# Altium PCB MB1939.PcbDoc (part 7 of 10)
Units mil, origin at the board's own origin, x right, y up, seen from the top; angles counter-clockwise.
Board outline 5910.64 x 4335.93 mil, 6 copper layers (Top Layer, l2_GND, L3_SIG, L4_VCC, L5_GND, Bottom Layer), stack 58.424 mil thick; 635 components, 489 nets, 2289 pads, 1388 vias.
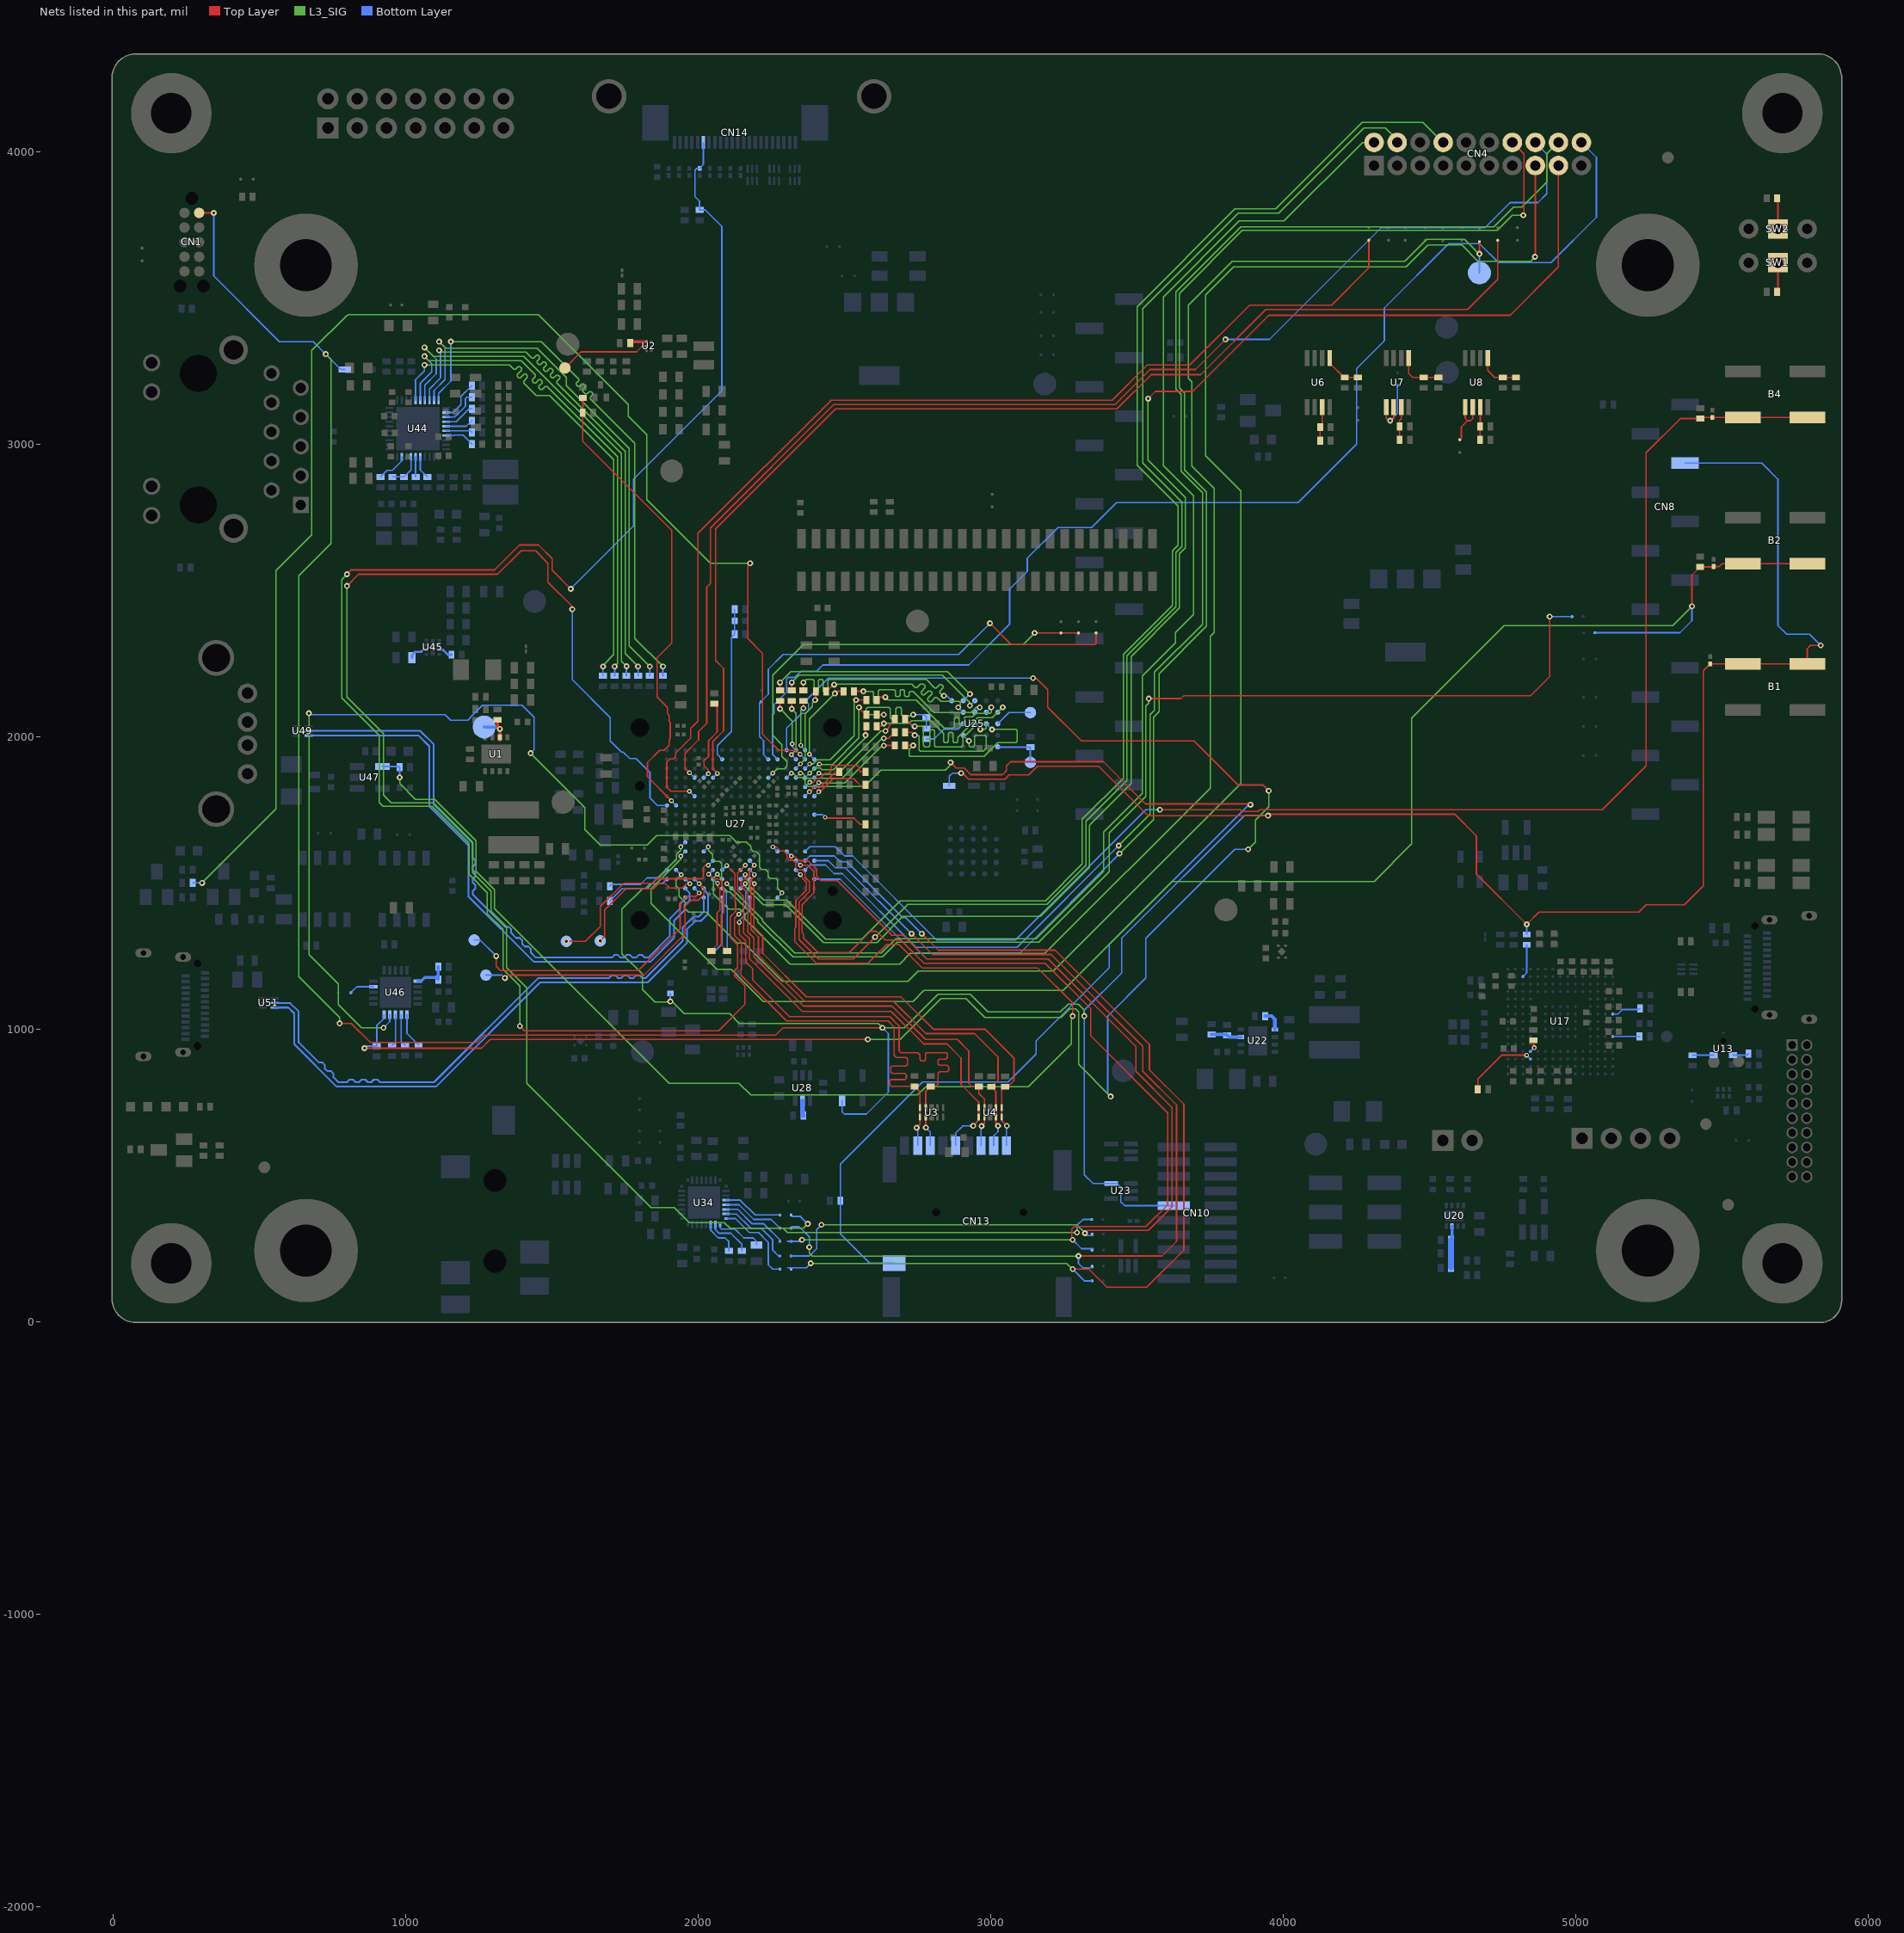
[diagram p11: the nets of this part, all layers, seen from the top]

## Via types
v1: diameter 20, hole 10, Top Layer to Bottom Layer, tented both sides, 1072 vias
v2: diameter 16, hole 8, Top Layer to Bottom Layer, tented both sides, 316 vias

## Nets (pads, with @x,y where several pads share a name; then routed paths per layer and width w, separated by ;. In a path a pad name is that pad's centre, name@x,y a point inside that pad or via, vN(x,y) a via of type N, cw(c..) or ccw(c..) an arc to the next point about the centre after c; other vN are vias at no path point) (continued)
NetR12_2: R12.2 TP12.1 U1.2 | length 129.9
  Top Layer w10: R12.2@1315,2057.28 1315,2034 v1(1322.8,2026.2) U1.2@1322.8,1998.07 1322.8,1987.31 1322.73,1987.24
  Bottom Layer w10: TP12.1@1269,2033 1316,2033 v1(1322.8,2026.2)
NetR25_2: R25.2 U2.A1 | length 58.6
  Top Layer w10: R25.2@1767.72,3345 1772.72,3350 U2.A1@1824.25,3350
NetR26_1: R26.1 U17.C4 | length 253.7
  Top Layer w5: R26.1@4664.57,795 4664.57,830 4745.81,911.25 v2(4831.55,911.25)
  Bottom Layer w5: v2(4831.55,911.25) U17.C4@4844.33,898.47
NetR32_1: R32.1 U27.C6 | length 268.7
  Top Layer w5: R32.1@2045,1267.72 2065.28,1288 2065.28,1397.28 2075,1407 2075,1480 2066.49,1488.51 v2(2066.49,1499)
  Bottom Layer w5: U27.C6@2050.86,1513.03 2064.89,1499 v2(2066.49,1499)
NetR33_1: R33.1 U27.P5 | length 289.9
  Top Layer w5: v2(2035.49,1873.2) 2035.49,1875.62 2035,1876.11 2035,1886.19 2020.51,1900.68 2020.51,1917.5 2035.91,1932.9 2035.91,1986.21 2065.3,2015.6 2065.3,2101.98 R33.1@2055,2112.28
  Bottom Layer w5: U27.P5@2019.36,1859.49 2033.07,1873.2 v2(2035.49,1873.2)
NetR34_1: R34.1 U27.D6 | length 327.4
  Top Layer w5: v2(2035.9,1529.83) 2038.18,1529.83 2054.51,1513.5 2072.5,1513.5 2080.99,1505.01 2080.99,1490.01 2087,1484 2087,1398 2080,1391 2080,1287.72 R34.1@2100,1267.72
  Bottom Layer w5: v2(2035.9,1529.83) 2036.16,1529.83 U27.D6@2050.86,1544.53
NetR81_2: R81.2 R82.2 U6.3 | length 117.2
  Top Layer w5: R81.2@4125.8,3012.01 R82.2@4125.8,3058.01 4132.8,3065.02 U6.3@4132.8,3126.34
NetR83_2: R83.2 R84.2 U6.5 | length 133.9
  Top Layer w5: U6.5@4158.39,3293.66 4158.39,3276.61 4207.28,3227.72 R84.2@4255,3227.72
NetR85_2: R85.2 R86.2 U7.3 | length 113.6
  Top Layer w5: R85.2@4397.29,3015 4397.28,3081.28 4402.8,3086.8 U7.3@4402.8,3126.34
NetR87_2: R87.2 R88.2 U7.5 | length 159.4
  Top Layer w5: U7.5@4428.39,3293.66 4428.39,3241.61 4442.28,3227.72 R88.2@4530,3227.72
NetR89_2: R89.2 R90.2 U8.3 | length 111.6
  Top Layer w5: R89.2@4672.29,3015 R90.2@4672.29,3060 4672.8,3060.52 U8.3@4672.8,3126.34
NetR91_2: R91.2 R92.2 U8.5 | length 148.6
  Top Layer w5: U8.5@4698.39,3293.66 4698.39,3251.61 4722.28,3227.72 R92.2@4795,3227.72
NetR93_1: R93.1 U17.D4 | length 44.4
  Top Layer w5: R93.1@4855,962.28 4855,938.95 v2(4857.11,936.84)
  Bottom Layer w5: U17.D4@4844.33,924.06 v2(4857.11,936.84)
NetR102_1: R102.1 SW1.1 | length 100.9
  Top Layer w5: R102.1@5687.72,3520 5690,3522.28 SW1.1@5690,3620
NetR103_1: R103.1 SW2.1 | length 105.9
  Top Layer w5: R103.1@5687.72,3840 5690,3837.72 SW2.1@5690,3735
NetR104_1: R104.1 U13.4 | length 55
  Bottom Layer w5: U13.4@5536.68,911.66 5584.81,911.66 R104.1@5589.67,916.51
NetR106_2: R106.2 U13.2 | length 72.4
  Bottom Layer w5: R106.2@5398.68,910.72 5399.62,911.66 U13.2@5470.69,911.66
NetR109_1: R109.1 U17.J15 | length 101.2
  Bottom Layer w5: U17.J15@5125.83,1052.01 5143.46,1052 5158.85,1067.39 5214.94,1067.39 R109.1@5218.98,1071.42
NetR110_1: R110.1 U17.F15 | length 91.6
  Bottom Layer w5: U17.F15@5125.83,975.24 5217.04,975.24 R110.1@5217.29,975
NetR117_1: R117.1 U17.P3 | length 114.1
  Bottom Layer w5: U17.P3@4818.74,1179.96 4831.69,1192.91 R117.1@4831.69,1288.7
NetR126_1: R126.1 R127.1 R128.1 U20.7 | length 143.4
  Bottom Layer w10: R128.1@4572.72,280 4576.14,283.42 U20.7@4576.14,327.01
  Bottom Layer w20: R126.1@4572.72,185 R128.1@4572.72,280
NetR132_1: R132.1 U22.5 | length 73
  Bottom Layer w12: R132.1@3937.72,1045 3960,1045 3971.06,1033.94 U22.5@3971.07,998.89
NetR133_2: R133.2 R135.1 U22.3 | length 103.6
  Bottom Layer w12: R135.1@3755,982.28 3805.08,982.28 3814.05,973.31 U22.3@3854.92,973.3
NetR139_1: R139.1 TP6.1 U25.A5 | length 163.9
  Bottom Layer w5: U25.A5@3024.25,1965.27 3025.23,1964.29 R139.1@3135.51,1964.29 TP6.1@3135.51,1912.01
NetR141_2: R141.2 U25.C2 | length 147.6
  Bottom Layer w5: R141.2@2780,1992.28 2807.28,1992.28 2840,2025 2887.13,2025 U25.C2@2906.14,2044.01
NetR146_1: R146.1 U28.5 | length 52.8
  Bottom Layer w15: U28.5@2357.02,756.18 2357.01,707.21 R146.1@2359.73,704.49
NetR147_1: R147.1 U34.1 | length 164.4
  Bottom Layer w5: U34.1@2074.76,329.23 2074.76,322.14 2079.6,317.3 2125.9,317.3 2156.4,286.8 2188.3,286.8 2200,275.1 R147.1@2200,262.56
NetR160_2: R160.2 U44.20 | length 1908.8
  L3_SIG w4: v1(1155,3350) 1464,3350 1591.79,3222.21 1591.79,3216.55 1583.45,3208.21 1583.45,3202.55 1589.11,3196.89 1594.77,3196.89 1603.11,3205.23 1608.77,3205.23 1614.43,3199.57 1614.43,3193.91 1606.09,3185.57 1606.09,3179.91 1614.61,3171.39 1620.27,3171.39 1628.61,3179.73 1634.27,3179.73 1639.93,3174.07 1639.93,3168.41 1631.59,3160.07 1631.59,3154.41 1784,3002 1784,2336 v1(1880,2240)
  Bottom Layer w5: U44.20@1113.5,3149.29 1113.5,3173.5 1155,3215 v1(1155,3350) ; R160.2@1880,2207.72 v1(1880,2240)
NetR161_2: R161.2 U44.19 | length 1847.7
  L3_SIG w4: v1(1115,3350) 1138,3327 1450,3327 1550,3227 1550,3199 1764,2985 1764,2311 v1(1835,2240)
  Bottom Layer w5: U44.19@1097.75,3149.29 1097.75,3182.75 1135,3220 1135,3330 v1(1115,3350) ; R161.2@1835,2207.72 v1(1835,2240)
NetR162_2: R162.2 U44.18 | length 1885.7
  L3_SIG w4: v1(1115,3320) 1120,3315 1412,3315 1432.86,3294.14 1438.52,3294.14 1447.86,3303.48 1453.52,3303.48 1459.18,3297.82 1459.18,3292.16 1449.84,3282.82 1449.84,3277.16 1455.5,3271.5 1461.16,3271.5 1470.5,3280.84 1476.16,3280.84 1481.82,3275.18 1481.82,3269.52 1472.48,3260.18 1472.48,3254.52 1478.14,3248.86 1483.8,3248.86 1493.14,3258.2 1498.8,3258.2 1504.46,3252.54 1504.46,3246.88 1495.12,3237.54 1495.12,3231.88 1500.78,3226.22 1506.44,3226.22 1515.78,3235.56 1521.44,3235.56 1527.1,3229.9 1527.1,3224.24 1517.76,3214.9 1517.76,3209.24 1751.52,2975.48 1751.52,2283.48 v1(1795,2240)
  Bottom Layer w5: U44.18@1082.01,3149.29 1082,3188.22 1120,3226.22 1120,3315 v1(1115,3320) ; R162.2@1795,2207.72 v1(1795,2240)
NetR166_2: R166.2 U44.17 | length 1803.4
  L3_SIG w4: v1(1065,3330) 1095,3300 1405,3300 1738,2967 1738,2258.04 v1(1755.52,2240.52)
  Bottom Layer w5: v1(1065,3330) 1105,3290 1105,3240 1066.25,3201.25 U44.17@1066.25,3149.29 ; R166.2@1755,2207.72 1755,2240 v1(1755.52,2240.52)
NetR169_2: R169.2 U44.16 | length 1806.5
  L3_SIG w4: v1(1065,3300) 1080,3285 1396,3285 1444.37,3236.63 1444.37,3230.97 1433.53,3220.13 1433.53,3214.47 1439.19,3208.81 1444.85,3208.81 1455.69,3219.65 1461.35,3219.65 1467.01,3213.99 1467.01,3208.33 1456.17,3197.49 1456.17,3191.83 1461.83,3186.17 1467.49,3186.17 1478.33,3197.01 1483.99,3197.01 1724.52,2956.48 1724.52,2249.52 v1(1715,2240)
  Bottom Layer w5: U44.16@1050.51,3149.29 1050.5,3206.72 1090,3246.22 1090,3275 v1(1065,3300) ; R169.2@1715,2207.72 v1(1715,2240)
NetR172_2: R172.2 U44.15 | length 1756.2
  L3_SIG w4: v1(1065,3270) 1356,3270 1370.69,3255.31 1376.35,3255.31 1385.69,3264.65 1391.35,3264.65 1397.01,3258.99 1397.01,3253.33 1381.67,3237.99 1381.67,3232.33 1387.33,3226.67 1392.99,3226.67 1405.33,3239.01 1410.99,3239.01 1416.65,3233.35 1416.65,3227.69 1403.81,3214.85 1403.81,3209.19 1447,3166 1493,3166 1712,2947 1712,2280.96 1675.52,2244.48 v1(1675.52,2240)
  Bottom Layer w5: U44.15@1034.76,3149.29 1034.76,3219.76 1065,3250 v1(1065,3270) ; R172.2@1675,2207.72 1675,2239.48 v1(1675.52,2240)
NetR180_2: R180.2 U44.27 | length 101.1
  Bottom Layer w5: U44.27@1139.09,3029.21 1164.47,3029.21 1165.46,3030.2 1197.08,3030.2 R180.2@1227.29,3000
NetR181_2: R181.2 U44.26 | length 90.2
  Bottom Layer w5: U44.26@1139.1,3044.95 1222.33,3044.95 R181.2@1227.29,3040
NetR182_2: R182.2 U44.25 | length 96.2
  Bottom Layer w5: U44.25@1139.09,3060.7 1207.65,3060.7 1226.95,3080 R182.2@1227.29,3080
NetR183_2: R183.2 U44.24 | length 106.2
  Bottom Layer w5: U44.24@1139.09,3076.45 1173.89,3076.45 1217.44,3120 R183.2@1227.29,3120
NetR184_2: R184.2 U44.23 | length 131.6
  Bottom Layer w5: U44.23@1139.09,3092.2 1168.42,3092.2 1205,3128.78 1205,3154.99 1210.01,3160 R184.2@1227.29,3160
NetR185_2: R185.2 U44.22 | length 142.6
  Bottom Layer w5: U44.22@1139.09,3107.95 1162.94,3107.94 1190,3135 1190,3162.71 R185.2@1227.29,3200
NetR189_2: R189.2 U45.3 | length 49.3
  Bottom Layer w7: U45.3@1115.2,2297.32 1127.43,2297.32
  Bottom Layer w8: 1127.43,2297.32 1144.75,2280 R189.2@1157.28,2280
NetR192_1: R192.1 R193.2 U46.11 | length 123.3
  Bottom Layer w10: U46.11@1041.8,1165.07 1055.07,1165.07 1066.5,1176.5 1104.79,1176.5 R192.1@1112.29,1169 R193.2@1112.29,1214
NetR196_2: R196.2 U44.35 | length 78.8
  Bottom Layer w5: U44.35@1050.51,2956.37 1050.5,2912.22 R196.2@1075,2887.72
NetR197_1: R197.1 U46.16 | length 120.1
  Bottom Layer w5: U46.16@1005.39,1049.91 1005.38,985.84 R197.1@1045.01,946.21
NetR198_2: R198.2 U44.36 | length 68.8
  Bottom Layer w5: U44.36@1034.76,2956.37 1034.76,2887.96 R198.2@1035,2887.72
NetR199_2: R199.2 U45.6 | length 65.8
  Bottom Layer w5: 1061.54,2297.32 U45.6@1071.89,2297.32
  Bottom Layer w8: R199.2@1022.56,2270 1022.56,2278.85 1033.71,2290 1054.22,2290 1061.54,2297.32
NetR202_2: R202.2 U46.17 | length 110.2
  Bottom Layer w5: U46.17@985.7,1049.91 985.69,958.53 R202.2@999.01,945.21
NetR203_1: R203.1 R205.2 U44.37 | length 118.6
  Bottom Layer w5: R205.2@955,2887.72 R203.1@995,2887.72 1019.01,2911.73 U44.37@1019.01,2956.37
NetR206_2: R206.2 U46.18 | length 110.7
  Bottom Layer w5: R206.2@954.01,944.21 966.01,956.21 U46.18@966.02,1049.91
NetR208_1: R208.1 U44.39 | length 109.1
  Bottom Layer w5: R208.1@915,2887.72 937.28,2910 955,2910 987.51,2942.51 U44.39@987.52,2956.37
NetR226_1: R226.1 U34.2 | length 151.2
  Bottom Layer w5: U34.2@2059.02,332.18 2059.02,314.98 2071.3,302.7 2112.3,302.7 2150,265 R226.1@2150,242.72
NetR227_1: R227.1 U34.3 | length 128.8
  Bottom Layer w5: U34.3@2043.27,332.18 2043.27,312.35 2068.74,286.87 2092.17,286.87 2105,274.04 R227.1@2105,242.72
NetSB47_2: SB47.2 U46.4 | length 85
  Bottom Layer w5: SB47.2@813.64,1125 834,1145.38 U46.4@890.23,1145.39
NetSB49_1: SB49.1 U8.1 U8.2 | length 178.2
  Top Layer w5: 4608,3020 4608,3058 4630,3080 ; U8.1@4621.61,3126.34 4621.61,3088.39 4630,3080 ; U8.2@4647.2,3126.34 4647.2,3087.2 4640,3080 4630,3080
NetSB51_1: SB51.1 U7.1 U7.2 | length 239.8
  Top Layer w5: U7.1@4351.61,3126.34 4351.61,3088.39 4360,3080 v1(4365,3080) 4370,3080 4377.2,3087.2 U7.2@4377.2,3126.34
  Bottom Layer w5: v1(4365,3080) 4390,3105 SB51.1@4390,3200.32
NetSB55_1: SB55.1 U34.28 | length 205.2
  Bottom Layer w5: U34.28@2095.43,415.84 2144.16,415.84 2195,365 SB55.1@2279.57,365
NetSB56_1: SB56.1 U34.29 | length 222.7
  Bottom Layer w5: U34.29@2095.43,400.1 2139.9,400.1 2190,350 2249.57,350 SB56.1@2279.57,320 2285,320
NetSB57_1: SB57.1 U34.30 | length 232.6
  Bottom Layer w5: U34.30@2095.43,384.35 2135.65,384.35 2185,335 2225,335 2279.57,280.43 SB57.1@2279.57,275
NetSB58_1: SB58.1 U34.32 | length 300.6
  Bottom Layer w5: U34.32@2095.43,352.85 2127.6,352.85 2175.45,305 2206.62,305 2240,271.62 2240,195 2255,180 SB58.1@2279.57,180
NetSB59_1: SB59.1 U34.31 | length 264.1
  Bottom Layer w5: U34.31@2095.43,368.6 2131.4,368.6 2180.26,319.74 2215.26,319.74 2255,280 2255,245 2275,225 SB59.1@2279.57,225
NetTP7_1: TP7.1 U25.C5 | length 127
  Bottom Layer w5: U25.C5@3024.25,2044.01 3062.25,2082.01 TP7.1@3135.51,2082.01
NetTP8_1: TP8.1 U27.C3 | length 474.5
  Top Layer w5: v1(1665.51,1302.01) 1681,1317.5 1681,1407.4 1753.6,1480 1847,1480 1864.3,1497.3 1888.61,1497.3 1903.11,1482.8 1934.45,1482.8 1934.49,1482.76 1946.51,1482.76 1961.05,1497.3 v2(1972.12,1497.3)
  Bottom Layer w5: U27.C3@1956.37,1513.03 v2(1972.12,1497.3)
NetTP9_1: TP9.1 U27.E6 | length 675.1
  Top Layer w5: v1(1550,1300) 1615,1300 1666,1351 1666,1419 1746,1499 1844,1499 1859,1514 2013,1514 2018,1519 2018,1522.48 2018.2,1522.68 2018.2,1534.7 2018,1534.9 2018,1552.99 2025.33,1560.32 v2(2035.09,1560.32)
  Bottom Layer w5: v2(2035.09,1560.32) 2050.8,1576.03 U27.E6@2050.86,1576.03
NetTP23_1: TP23.1 U27.C4 | length 989.2
  Top Layer w5: v1(1340,1175) 1350,1185 1815,1185 1956,1326 1956,1421 1976.01,1441.01 2001.01,1441.01 2020,1460 2020,1480.88 v2(2003.53,1497.35)
  Bottom Layer w5: TP23.1@1275,1185 1330,1185 v1(1340,1175) ; U27.C4@1987.87,1513.03 v2(2003.53,1497.35)
NetTP24_1: TP24.1 U27.B4 | length 1016.9
  Top Layer w5: v1(1310,1250) 1310,1215 1325,1200 1794.99,1200 1938.5,1343.51 1938.5,1432.19 1961.32,1455.01 1992.82,1455.01 v2(2003.61,1465.8)
  Bottom Layer w5: TP24.1@1235,1305 1255,1305 v1(1310,1250) ; U27.B4@1987.87,1481.54 v2(2003.61,1465.8)
NetTP25_1: TP25.1 U2.B1 | length 310
  Top Layer w5: TP25.1@1545,3260 1600,3315 1790,3315 1809.25,3334.25 U2.B1@1824.25,3334.25
NRST: B1.1 B1.2 C198.2 CN1.10 CN8.3 CN10.10 D4.2 D6.2 D7.2 R117.2 U9.1 U23.5 U27.G3 | length 15108.3
  Top Layer w5: CN1.10@295.02,3790 v1(345,3790) ; v1(775,1020) 815,1020 880,955 1245,955 1270,980 2265,980 2290,1005 v1(2630,1005) ; v1(2898.86,1875.33) 2903.67,1875.33 2924,1855 3049,1855 3063,1869 3130,1869 3160,1899 3369.01,1899 3538.01,1730 v1(3948,1730) 3953,1735 4585,1735 4660,1660 4660,1530 v1(4831.69,1358.31) 4873.38,1400 5215,1400 5240,1425 5370,1425 5435,1490 5435,2225 U9.1@5458.74,2248.74 B1.1@5569.77,2248.74 B1.2@5790.24,2248.74 5790.24,2300.24 5801.5,2311.5 v1(5836.5,2311.5)
  L3_SIG w4: v1(727.5,3307.5) 745,3290 745,2660 635,2550 635,1180 775,1040 v1(775,1020) ; v2(1940.59,1623.23) 1940.59,1611.61 1926.6,1597.62 1926.6,1581.6 1825,1480 1810,1480 1740,1410 1740,1258.24 1810,1188.24 1810,1135 1852,1093 1903,1093 v1(1905,1095) 1910.96,1095 1952.96,1053 2108.26,1053 2141.26,1020 2615,1020 v1(2630,1005) 2705,1005 2820,1120 2930,1120 2991,1059 3238,1059 3264,1085 3264,1085.5 3299.5,1085.5 3320,1065 v1(3320,1045)
  Bottom Layer w5: v1(345,3790) 345,3574.8 569.8,3350 685,3350 v1(727.5,3307.5) 780,3255 D7.2@792.88,3255 ; v1(1905,1095) C198.2@1905,1122.28 ; v2(1940.59,1623.23) U27.G3@1956.37,1639.02 ; D6.2@2492.01,757.36 2492.01,717.99 2500,710 2575,710 2650,785 2650,985 v1(2630,1005) ; D4.2@2858.39,1832.01 2858.38,1864.7 2869.01,1875.33 v1(2898.86,1875.33) ; CN10.10@3625.53,397.01 3457.99,397.01 3445,410 3445,460.01 3432.41,472.6 3350,472.6 3320,502.6 v1(3320,1045) 3320,1065 3447.5,1192.5 3447.5,1311.27 3866.23,1730 v1(3948,1730) ; R117.2@4831.69,1324.14 v1(4831.69,1358.31) ; CN8.3@5372.5,2935 5635,2935 5690,2880 5690,2380 5720,2350 5798,2350 v1(5836.5,2311.5)
NRST_CAM: CN14.17 R221.2 U27.D7 U38.1 | length 5959.3
  Top Layer w5: v1(800,2555) 815,2570 1305,2570 1390,2655 1455,2655 1501,2609 1501,2569 v1(1565,2505) ; v1(1391,1011) 1407,995 2070,995 2160,1085 2160,1148 2125,1183 2125,1201.13 2135,1211.13 2135,1289 2110,1314 2110,1384.31 2128.28,1402.59 2128.28,1433.35 2126,1435.63 2126,1531.3 v2(2097.56,1559.74)
  L3_SIG w4: v1(800,2555) 782,2537 782,2133 910,2005 910,1775 923.73,1761.27 1090.7,1761.27 1217,1634.97 1217,1529.97 1280,1466.97 1280,1395 1334,1341 1334,1205.04 1391,1148.04 v1(1391,1011)
  Bottom Layer w5: v1(1565,2505) 1780,2720 1780,2880.98 2081.3,3182.28 2081.3,3743.7 2025,3800 R221.2@2005,3800 2005,3830 1989.02,3845.98 1989.02,3936.32 1995,3942.3 U38.1@2005,3942.31 2018.03,3955.33 CN14.17@2018.04,4030.71
  Bottom Layer w10: U27.D7@2082.35,1544.53 v2(2097.56,1559.74)
OCTOSPI_CLK: R71.1 U25.B2 | length 516.2
  Top Layer w5: R71.1@2707.72,2015 2730,2015 v1(2740,2005)
  L3_SIG w4: v1(2740,2005) 2751,2005 2755,2001 2755,1954 2759,1950 2975,1950 2984.76,1959.76 2984.76,2000.24 2980.33,2004.67 2969.53,2004.67 2969.44,2004.76 2949.76,2004.76 2945.29,2000.29 2945.29,1970.29 2940,1965 2930,1965 2925.39,1969.61 v1(2925.39,1985.39)
  Bottom Layer w5: U25.B2@2906.14,2004.64 v1(2925.39,1985.39)
OCTOSPI_DQS: R72.1 U25.C3 | length 569.1
  Top Layer w5: R72.1@2707.72,2060 2732.72,2035 v1(2740,2035)
  L3_SIG w4: v1(2740,2035) 2765,2035 2770,2030 2770,1970 2775,1965 2787.65,1965 2791.65,1969 2791.65,2019 2795.65,2023 2803.65,2023 2807.65,2019 2807.65,1969 2811.65,1965 2901,1965 2905,1969 2905,1994.99 2955.01,2045 2981,2045 2985,2041 2985,2030 2979.76,2024.76 v1(2964.76,2024.76)
  Bottom Layer w5: U25.C3@2945.51,2044.01 v1(2964.76,2024.76)
OCTOSPI_IO0: R52.1 U25.D3 | length 634.5
  Top Layer w5: R52.1@2532.72,2155 v1(2565,2155)
  L3_SIG w4: v1(2565,2155) 2595.89,2155 2599.89,2151 2599.89,2119 2603.89,2115 2611.89,2115 2615.89,2119 2615.89,2156 2619.89,2160 2670.01,2160 2674.01,2156 2674.01,2141 2678.01,2137 2686.01,2137 2690.01,2141 2690.01,2156 2694.01,2160 2702.01,2160 2706.01,2156 2706.01,2141 2710.01,2137 2718.01,2137 2722.01,2141 2722.01,2151 2726.01,2155 2735.01,2155 2807.1,2082.91 2932.91,2082.91 2950.26,2100.26 v1(2962.39,2100.26)
  Bottom Layer w5: U25.D3@2945.51,2083.38 v1(2962.39,2100.26)
OCTOSPI_IO1: R42.1 U25.D2 | length 643
  Top Layer w5: R42.1@2437.72,2155 2440,2155 2462.65,2177.65 v1(2465,2177.65)
  L3_SIG w4: v1(2465,2177.65) 2467.35,2180 2730,2180 2742.17,2167.83 2747.83,2167.83 2760,2180 2770,2180 2776.4,2173.6 2776.4,2167.96 2762.04,2153.61 2762.04,2147.97 2767.72,2142.29 2773.36,2142.29 2787.72,2156.64 2793.36,2156.64 2799.04,2150.96 2799.04,2145.32 2784.68,2130.97 2784.68,2125.33 2790.36,2119.65 2796,2119.65 2810.36,2134 2816,2134 2830,2120 2892.66,2120 2896.67,2115.99 2896.67,2107.67 v1(2889.26,2100.26)
  Bottom Layer w5: v1(2889.26,2100.26) U25.D2@2906.14,2083.38
OCTOSPI_IO2: R70.1 U25.C4 | length 610.8
  Top Layer w5: R70.1@2707.72,1970 v1(2735,1970)
  L3_SIG w4: v1(2735,1970) 2720.83,1955.83 2720.83,1936.01 2724.84,1932 2977,1932 3025,1980 3086,1980 3090,1984 3090,2020.44 3086,2024.44 v1(3004.45,2024.44)
  Bottom Layer w5: U25.C4@2984.88,2044.01 v1(3004.45,2024.44)
OCTOSPI_IO3: R67.1 U25.D4 | length 561.5
  Top Layer w5: R67.1@2607.72,2125 R67.1@2610.72,2125 2612.72,2125 2622.72,2135 v1(2640,2135)
  L3_SIG w4: v1(2640,2135) 2650,2125 2745,2125 2840,2030 2872,2030 2876,2034 2876,2061 2880,2065 2888,2065 2892,2061 2892,2044 2896,2040 2905,2040 2910,2045 2910,2063.5 2914,2067.5 2937.5,2067.5 2950,2080 2997.76,2080 3001.76,2084 v1(3001.76,2100.26)
  Bottom Layer w5: U25.D4@2984.88,2083.38 v1(3001.76,2100.26)
OCTOSPI_IO4: R65.1 U25.D5 | length 630.5
  Top Layer w5: R65.1@2607.72,2035 R65.1@2610.72,2035 2625,2035 v1(2635,2045)
  L3_SIG w4: v1(2635,2045) 2720,2045 2730,2055 2795,2055 2839,2011 2839,1984 2843,1980 2851,1980 2855,1984 2855,2011 2859,2015 2867,2015 2871,2011 2871,1984 2875,1980 2883,1980 2887,1984 2887,1997 2955,2065 3005.87,2065 v1(3041.13,2100.26)
  Bottom Layer w5: U25.D5@3024.25,2083.38 v1(3041.13,2100.26)
OCTOSPI_IO5: R39.1 U25.E3 | length 719.4
  Top Layer w5: R39.1@2320,2157.72 v1(2320,2185)
  L3_SIG w4: v1(2320,2185) 2345,2210 2835,2210 2928.63,2116.37 v1(2928.63,2105.87)
  Bottom Layer w5: v1(2928.63,2105.87) U25.E3@2945.51,2122.75
OCTOSPI_IO6: R37.1 U25.E2 | length 756
  Top Layer w5: R37.1@2280,2157.72 v1(2280,2185.01)
  L3_SIG w4: v1(2280,2185.01) 2316.99,2222 2853.01,2222 v1(2929.2,2145.81)
  Bottom Layer w5: U25.E2@2906.14,2122.75 v1(2929.2,2145.81)
OCTOSPI_IO7: R40.1 U25.E1 | length 769.5
  Top Layer w5: R40.1@2360,2157.72 v1(2360,2185)
  L3_SIG w4: v1(2360,2185) 2370,2195 2392,2195 2396,2191 2396,2154 2400,2150 2408,2150 2412,2154 2412,2191 2416,2195 2424,2195 2428,2191 2428,2154 2432,2150 2440,2150 2444,2154 2444,2191 2448,2195 2780,2195 2808.47,2166.53 2814.13,2166.53 2825.97,2178.37 2831.63,2178.37 2837.29,2172.71 2837.29,2167.05 2825.45,2155.21 2825.45,2149.55 2835,2140 v1(2840,2140)
  Bottom Layer w5: v1(2840,2140) 2849.52,2140 U25.E1@2866.77,2122.75
OCTOSPI_NCS: R66.1 R141.1 R142.1 | length 450.3
  Top Layer w5: R66.1@2607.72,2075 R66.1@2610.72,2075 v1(2635,2075)
  L3_SIG w4: v1(2635,2075) 2579.7,2075 2575,2079.7 2575,2095.3 2579.7,2100 2652.44,2100 2657.14,2095.3 2657.14,2064.7 2661.84,2060 2671.24,2060 2675.94,2064.7 2675.94,2095.3 2680.64,2100 2691,2100 2695,2096 2695,2075 2700,2070 2730,2070 v1(2735,2075)
  Bottom Layer w5: v1(2735,2075) 2772.28,2075 R142.1@2780,2067.28 R141.1@2780,2027.72
OTG1_HS_N: U27.A5 U51.5 | length 2015.1
  Bottom Layer w6.1: U51.5@553.67,1090 554.63,1089.04 606.26,1089.04 635,1060.3 635,955 703.98,886.02 716.44,886.02 724.92,877.53 724.92,865.08 733.4,856.6 745.86,856.6 754.34,848.11 754.34,835.66 771.1,818.9 800.1,818.9 808.9,827.7 820.9,827.7 829.7,818.9 841.7,818.9 850.5,827.7 862.5,827.7 871.3,818.9 883.3,818.9 892.1,827.7 904.1,827.7 912.9,818.9 1097.68,818.9 1453.78,1175 1696.2,1175 1705,1183.8 1717,1183.8 1725.8,1175 1737.8,1175 1746.6,1183.8 1758.6,1183.8 1767.4,1175 1779.4,1175 1788.2,1183.8 1800.2,1183.8 1809,1175 1821,1175 1947,1301 1947,1347.23 1984.77,1385 2003,1385 2019.42,1401.42 U27.A5@2019.36,1450.04 U27.A5@2019.36,1450.04
OTG1_HS_P: U27.B5 U51.6 | length 2017.2
  Bottom Layer w6.1: U51.6@553.67,1074.04 600.04,1074.04 620,1054.08 620,948.78 764.88,803.9 1103.9,803.9 1460,1160 1827.22,1160 1962,1294.78 1962,1341.01 1990.99,1370 2009.22,1370 2034.42,1395.2 2034.42,1458.6 U27.B5@2019.36,1481.54
OTG2_HSD_N: U27.A3 U49.5 | length 2027.2
  Bottom Layer w6.1: U49.5@669.32,2019.35 1050.65,2019.35 1096.6,1973.4 1096.6,1768.4 1230,1635 1230,1585.1 1238.8,1576.3 1238.8,1564.3 1230,1555.5 1230,1543.5 1238.8,1534.7 1238.8,1522.7 1230,1513.9 1230,1501.9 1238.8,1493.1 1238.8,1481.1 1230,1472.3 1230,1460.3 1311.06,1379.24 ; 1311.08,1379.24 1332,1358.3 1340.48,1349.82 1352.94,1349.82 1361.42,1341.33 1361.42,1328.88 1378.18,1312.12 1390.64,1312.12 1399.12,1303.63 1399.12,1291.18 1407.6,1282.7 1420.06,1282.7 1428.54,1274.21 1428.54,1261.76 1445.3,1245 1705.19,1245 1713.99,1253.8 1725.99,1253.8 1734.79,1245 1746.79,1245 1755.59,1253.8 1767.59,1253.8 1776.39,1245 1788.39,1245 1797.19,1253.8 1809.19,1253.8 1817.99,1245 1829.99,1245 1903,1318.01 1903,1377.22 1939,1413.22 1939,1428.63 1956.37,1446 U27.A3@1956.37,1450.04 U27.A3@1956.12,1449.79
OTG2_HSD_P: U27.B3 U49.6 | length 2024.5
  Bottom Layer w6.1: U49.6@668.67,2004.25 668.77,2004.35 1044.43,2004.35 1081.6,1967.18 1081.6,1762.18 1215,1628.78 1215,1454.08 1439.08,1230 1836.21,1230 1918,1311.79 1918,1371 1953.5,1406.5 1953.5,1423.5 1971.37,1441.37 1971.37,1465.28 1956.37,1480.28 U27.B3@1956.37,1481.54
PA4: R210.2 U27.U14 U46.20 | length 6372.5
  Top Layer w5: v1(860,935) 1260,935 1290,965 v1(2580,965) ; v1(3145,2200) 3155,2200 3195,2160 3195,2100 3310,1985 3695,1985 3845,1835 3930,1835 v1(3950,1815)
  L3_SIG w4: v1(2580,965) 2690,965 2830,1105 2915,1105 2980,1040 3240,1040 3270,1070 3290,1070 3300,1060 3300,880 v1(3410,770) ; v1(3880,1615) 3905,1640 3905,1715 3950,1760 v1(3950,1815)
  Bottom Layer w5: v1(860,935) 867.21,942.21 R210.2@902.01,942.21 902.01,1012.01 926.64,1036.64 U46.20@926.64,1049.91 ; U27.U14@2302.83,1953.98 2302.82,2028.92 2353.64,2079.74 2367.25,2079.74 2377.5,2089.99 2377.5,2112.5 2373,2117 2373,2128 2445,2200 v1(3145,2200) ; v1(3410,770) 3400,780 3400,1045 3530,1175 3530,1311 3834,1615 v1(3880,1615)
PA11: C151.2 R151.2 R152.1 U27.T7 | length 544.2
  Bottom Layer w5: U27.T7@2082.34,1922.48 2065.42,1939.4 2065.42,1969.02 2113.95,2017.55 2114.06,2215.27 2114.06,2339.06 R151.2@2125.01,2350 C151.2@2124.99,2395 R152.1@2125.01,2435
PA15: SB6.2 SB7.2 U27.P12 | length 1517.2
  Top Layer w5: v1(3150,2354.33) 3299.68,2354.33 SB7.2@3300,2354.65
  L3_SIG w4: v2(2255.48,1875.27) 2270,1889.79 2294.79,1889.79 2304.47,1899.47 2304.47,1915.54 2286.97,1933.04 2286.97,1971.97 2255,2003.94 2255,2210 2359.8,2314.8 3110.47,2314.8 v1(3150,2354.33)
  Bottom Layer w5: U27.P12@2239.84,1859.49 2239.83,1859.62 v2(2255.48,1875.27)
PB0: SB26.2 SB57.2 U27.E15 | length 3703.6
  Top Layer w5: v2(2350.02,1560.3) 2374.7,1560.3 2395.98,1539.02 2395.98,1465.98 2355,1425 2355,1331.22 2360,1326.22 2360,1312.08 2410.08,1262 2517,1262 2590,1335 2609.75,1335 2639.75,1305 2692.32,1305 2772,1225.32 3186.48,1225.32 3341.55,1070.25 3341.55,977.65 3605,714.2 3605,400 3530.5,325.5 3285.5,325.5 3277.5,317.5 3277.5,282.5 v1(3280,280)
  L3_SIG w4: v1(2355,280) v1(3280,280)
  Bottom Layer w5: 2305.65,275 SB57.2@2317.95,275 2350,275 v1(2355,280) ; U27.E15@2334.33,1576.03 v2(2350.02,1560.3) ; v1(3280,280) 3310,250 3350,250
PB3: CN4.12 U27.F13 | length 4846.3
  Top Layer w5: v2(2255.86,1623.01) 2266.71,1623.01 2280.96,1608.76 2293.28,1608.76 2304.02,1597.78 2304.02,1585.79 2312.51,1577.3 2326.23,1577.3 2333.02,1570.51 2333.02,1552.51 2341.52,1544.01 2356.52,1544.01 2365.52,1535.01 2365.52,1519.49 2380,1505.01 2380,1470.01 2345,1435.01 2345,1305.86 2410.86,1240 2530,1240 v1(2605,1315)
  L3_SIG w4: v1(2605,1315) 2716.86,1426.86 3191.86,1426.86 3325,1560 3325,1710 3465,1850 3465,2276.05 3633,2444.05 3633,2629.99 3653,2649.99 3653,2802 3520,2935 3520,3463 3846,3789 3984,3789 4275.71,4080.71 4349.29,4080.71 4388.78,4041.22 CN4.12@4388.78,4005
  Bottom Layer w5: v2(2255.86,1623.01) U27.F13@2271.33,1607.52
PB4: SB8.2 SB43.2 U27.T12 | length 1584.3
  Top Layer w5: v1(2997.5,2387.5) 3070,2315 3355,2315 3360,2320 SB8.2@3360,2354.65
  Bottom Layer w5: U27.T12@2239.84,1922.48 2239.74,1922.48 2224.02,1938.2 2224.02,1985.98 2210,2000 2210,2114.33 SB43.2@2215,2119.33 2215,2120 2240,2145 2240,2230 2290.8,2280.8 2890.8,2280.8 v1(2997.5,2387.5)
PB6: SB28.2 SB56.2 U27.E17 | length 3590.7
  Top Layer w5: v1(2729.5,1326.5) 2800.68,1255.32 3206.48,1255.32 3520,941.8 3520,856 3635,741 3635,275 3585,225 v1(3300,225)
  L3_SIG w4: v1(2380,255) 2380,235 2390,225 v1(3300,225)
  Bottom Layer w5: 2320,325 2345,325 2380,290 v1(2380,255) ; U27.E17@2397.32,1576.03 2429.43,1576.01 2445.52,1576 2469.51,1552.01 2502.99,1552.01 2728.5,1326.5 v1(2729.5,1326.5) ; v1(3300,225) 3300,199.49 3314.49,185 3350,185
PB7: SB27.2 SB58.2 U27.E16 | length 3732.9
  Top Layer w5: v1(2764.5,1326.5) 2820.68,1270.32 3220.14,1270.32 3542.23,948.23 3542.23,861.77 3660,744 3660,245 3533.01,118.01 3396.99,118.01 3335,180 v1(3280,180)
  L3_SIG w4: v1(2385,200) 3260,200 v1(3280,180)
  Bottom Layer w5: 2305,185 2370,185 v1(2385,200) ; U27.E16@2365.82,1576.03 2365.82,1576.09 2382.03,1592.3 2465.52,1592.3 2485.81,1572.01 2507.99,1572.01 2699,1381 2710,1381 v1(2764.5,1326.5) ; v1(3280,180) 3320,140 SB27.2@3346.61,140
PB8: CN4.19 U27.D16 | length 4962.7
  L3_SIG w4: v1(3437.5,1627.5) 3545,1735 3545,2075 3560,2090 3560,2220 3724,2384 3724,2832.98 3650,2906.98 3650,3171.02 3633,3188.02 3633,3519.98 3855.02,3742 4718.95,3742 4786.95,3810 4815.01,3810 4900.6,3895.59 4900.6,3991.34 CN4.19@4939.97,4030.71
  Bottom Layer w5: U27.D16@2365.82,1544.53 2365.82,1544.6 2382.62,1561.4 2435.52,1561.4 2464.91,1532.01 2492.99,1532.01 2745,1280 3090,1280 v1(3437.5,1627.5)
PB9: R201.2 U27.D15 U47.4 | length 4532.5
  Top Layer w5: v2(2350.02,1528.8) 2350.02,1524.98 2356.52,1518.48 2356.52,1515.76 2370,1502.28 2370,1475 2334.28,1439.28 2334.28,1349.21 2330,1344.93 2330,1299.64 2404.64,1225 2580,1225 2645,1290 2686.1,1290 2766.49,1209.61 3160.39,1209.61 3280,1090 v1(3280,1045)
  L3_SIG w4: v1(980.27,1860.27) 980.27,1839.73 1034,1786 1099.91,1786 1241,1644.91 1241,1539.91 1304,1476.91 1304,1412 1901,815 2140,815 2180,775 2750,775 2778.28,803.28 3128.28,803.28 3275,950 3275,1040 v1(3280,1045)
  Bottom Layer w5: U47.4@921.3,1897.91 977.87,1897.91 R201.2@980.28,1895.51 v1(980.27,1860.27) ; U27.D15@2334.33,1544.53 v2(2350.02,1528.8)
PC0: CN13.1 R77.1 U4.5 U4.6 U27.C10 | length 1609.1
  Top Layer w5: v2(2192.52,1497.3) 2191,1495.78 2191,1350 2221,1320 2221,1312.72 2221.06,1312.66 2221.06,1260.04 2370.05,1111.05 2692.95,1111.05 2804,1000 2980.3,1000 3079.7,900.6 3079.7,824.7 3058.28,803.28 R77.1@3049,803.28 3037.37,791.65 U4.6@3037.37,732.14 U4.5@3037.37,699.86 3037.37,687.63 v1(3055,670)
  Bottom Layer w5: U27.C10@2176.84,1513.03 U27.C10@2176.84,1513.03 v2(2192.52,1497.3) ; CN13.1@3053.71,602.35 3053.71,668.71 v1(3055,670)
PC2: CN13.5 U4.1 U4.10 U27.D9 | length 1609.3
  Top Layer w5: v2(2161.02,1560.3) 2135,1534.28 2135,1475 2155.83,1454.17 2155.83,1329.15 2176,1308.98 2176,1294.06 2176.06,1294 2176.06,1241 2356.06,1061 2659.78,1061 2770.78,950 2850,950 2898.6,901.4 2898.6,811.4 2958.63,751.37 U4.10@2958.63,732.14 2958.63,688.63 v1(2940,670)
  Bottom Layer w5: U27.D9@2145.35,1544.53 2145.34,1544.62 v2(2161.02,1560.3) ; CN13.5@2880.48,602.35 2880.48,645.48 2905,670 v1(2940,670)
PC3: CN13.3 R75.1 U4.2 U4.9 U27.E10 | length 1609.7
  Top Layer w5: v2(2192.54,1560.3) 2175.52,1543.28 2175.52,1522.79 2167.03,1514.3 2157.59,1514.3 2146.6,1503.31 2146.6,1488.41 2170.29,1464.72 2170.29,1332.66 2191,1311.95 2191,1300.28 2191.06,1300.22 2191.06,1247.6 2359.66,1079 2663,1079 2777,965 2885.8,965 2925,925.8 2925,814.7 2935.42,804.28 R75.1@2960,804.28 2960,780 2978.32,761.68 U4.9@2978.32,732.14 U4.2@2978.32,699.86 2978.32,678.31 v1(2969,669)
  Bottom Layer w5: U27.E10@2176.84,1576.03 v2(2192.54,1560.3) ; CN13.3@2967.09,602.35 2967.09,667.09 v1(2969,669)
PC4: CN13.7 R74.1 U3.2 U3.9 U27.A10 | length 1615.3
  Top Layer w5: v2(2140.56,1365.56) 2140.56,1324.44 2163,1302 2163,1230 2186,1207 2186,1169 2312,1043 2655.22,1043 2687,1011.22 2687,926.1 2693.2,919.91 2750.7,919.91 2758.1,912.5 2758.1,896.4 2762.7,891.8 2772.7,891.8 2777.2,896.3 2777.2,916.5 2780.6,919.91 2847.8,919.91 2852.5,915.2 2852.5,903.4 2846.7,897.6 2824.5,897.6 2820,893.1 2820,881.6 2824.7,876.9 2850.7,876.9 2856.6,871 2856.6,859.3 2852.5,855.2 2826.1,855.2 2820,849.1 2820,812 2812.57,804.57 R74.1@2795,804.57 2778.32,787.88 U3.9@2778.32,732.14 U3.2@2778.32,699.86 v1(2778.32,664)
  Bottom Layer w5: v2(2140.56,1365.56) 2140.56,1371.64 2176.84,1407.92 U27.A10@2176.84,1450.04 ; v1(2778.32,664) 2793.87,648.45 CN13.7@2793.87,602.35
PC5: CN13.8 R73.1 U3.1 U3.10 U27.B10 | length 1618.3
  Top Layer w5: v2(2139.5,1393.3) 2138.82,1393.3 2135.58,1390.06 2134.94,1390.06 2125,1380.12 2125,1320.01 2148,1297.01 2148,1205.75 2146.5,1204.25 2146.5,1184.5 2303,1028 2649,1028 2669.9,1007.1 2669.9,910.7 2677.4,903.2 2711.5,903.2 2716,898.7 2716,880.4 2709.6,874 2662.6,874 2658.3,869.7 2658.3,853.6 2662.7,849.2 2706.8,849.2 2712.1,843.9 2712.1,833.3 2706.4,827.6 2658.3,827.6 2654.4,823.7 2654.4,809.9 2659.73,804.57 R73.1@2740,804.57 2758.63,785.94 U3.10@2758.63,732.14 U3.1@2758.63,699.86 2758.63,674.63 v1(2747,663)
  Bottom Layer w5: v2(2139.5,1393.3) 2139.5,1393.98 2163.25,1417.73 2163.25,1467.95 U27.B10@2176.84,1481.54 U27.B10@2176.84,1481.54 U27.B10@2176.84,1481.54 ; v1(2747,663) 2750.56,659.44 CN13.8@2750.56,602.35
PC6: CN4.9 U27.B9 | length 5094.8
  Top Layer w5: v1(3538,3155) 3563,3180 3690,3180 3950,3440 4775,3440 4939.96,3604.96 CN4.9@4939.96,3926.26
  L3_SIG w4: v2(2161.1,1497.3) 2161.1,1486.9 2223,1425 2300,1425 2429,1296 2611,1296 2700,1385 3170,1385 3338,1553 3338,1696.98 3340,1698.98 3340,1700 3480,1840 3480,2274.05 3645,2439.05 3645,2625.01 3665,2645.01 3665,2818.02 3538,2945.02 v1(3538,3155)
  Bottom Layer w5: U27.B9@2145.35,1481.54 2145.41,1481.54 2145.41,1481.61 v2(2161.1,1497.3)
PC7: CN4.14 U27.C9 | length 4819.5
  L3_SIG w4: v2(2161.02,1528.8) 2161.02,1517.18 2175.1,1503.1 2175.1,1491.5 2224.6,1442 2303,1442 2437,1308 2559.14,1308 2690,1438.86 3186.88,1438.86 3313,1564.98 3313,1718 3453,1858 3453,2281.03 3621,2449.03 3621,2634.97 3640,2653.97 3640,2788.02 3500,2928.02 3500,3469 3835,3804 3974,3804 4270,4100 4476.97,4100 CN4.14@4546.26,4030.71
  Bottom Layer w5: U27.C9@2145.35,1513.03 2145.34,1513.12 v2(2161.02,1528.8)
PC9: SB16.2 TP3.1 U27.C7 | length 5059.3
  Top Layer w5: v1(4670,3650) SB16.2@4670,3691.38
  L3_SIG w4: v2(2066.06,1529.55) 2052.49,1515.98 2052.49,1462.51 2104.26,1410.74 2142.94,1410.74 2159.5,1394.18 2159.5,1377.52 2314.02,1223 2688.98,1223 2724.57,1258.59 3184.38,1258.59 3749.89,1824.1 3749.89,2342.89 3763,2356 3763,2848.98 3687,2924.98 3687,3213 3675,3225 3675,3475 3825,3625 4415,3625 4490,3700 4620,3700 v1(4670,3650)
  Bottom Layer w5: v2(2066.06,1529.55) 2066.69,1528.92 2066.69,1528.69 U27.C7@2082.35,1513.03 ; TP3.1@4670,3585 v1(4670,3650)
PC11: CN4.11 U27.B8 | length 4599
  L3_SIG w4: v2(2098.08,1497.23) 2220.5,1374.81 2220.5,1369.5 2330,1260 2625.94,1260 2675.44,1309.5 3155.5,1309.5 3385.5,1539.5 3385.5,1673.5 3518,1806 3518,2207.97 3631,2320.97 3631,2356 3693,2418 3693,2823.98 3590,2926.98 3590,3503 3849,3762 4002,3762 4270.71,4030.71 CN4.11@4310.04,4030.71
  Bottom Layer w5: v2(2098.08,1497.23) U27.B8@2113.85,1481.54 U27.B8@2113.85,1481.54
PC13: B2.3 B2.4 R225.2 SB44.2 U10.1 U27.F3 | length 5646.4
  Top Layer w5: v1(5396.4,2445.3) 5396.4,2552.11 R225.2@5424.29,2580 5468.58,2580 U10.1@5470,2581.42 5490,2581.42 5499.84,2591.26 B2.3@5569.77,2591.26 B2.4@5790.24,2591.26
  L3_SIG w4: v2(1940.6,1591.82) 1940.6,1580.6 1840,1480 1840,1430 2065,1205 2113.02,1205 2223.02,1095 2733.96,1095 2771.96,1133 3248,1133 3620,1505 4310,1505 4439,1634 4439,2064 4755,2380 5331.1,2380 v1(5396.4,2445.3)
  Bottom Layer w5: v2(1940.6,1591.82) 1956.3,1607.52 U27.F3@1956.37,1607.52 ; SB44.2@5065,2355 5355,2355 5396.4,2396.4 v1(5396.4,2445.3)
PC14: R171.2 U27.D1 | length 218.4
  Bottom Layer w5: R171.2@1698.11,1488.69 1704.42,1495 1803.32,1495 1825.62,1517.3 1866.15,1517.3 U27.D1@1893.38,1544.53
PC15: R170.2 U27.C1 | length 226.1
  Bottom Layer w5: R170.2@1698.11,1438.69 1739.42,1480 1818.32,1480 1835.62,1497.3 1877.65,1497.3 U27.C1@1893.38,1513.03
PD10: U27.A13 U46.19 | length 3428.4
  L3_SIG w4: v1(670.01,2080) 670.01,1255 770.01,1155 770.01,1085 850.01,1005 v1(925.01,1005) ; v1(1427.72,1943.28) 1613,1758 1613,1683 1666.17,1629.83 1825.83,1629.83 1858,1662 2107.99,1662 2129.99,1640 2165,1640 2179.93,1625.07 2179.93,1616.13 2188.13,1607.93 2197.07,1607.93 2209.16,1595.84 2209.16,1554.59 2217.75,1546 2230,1546 2239,1537 2239,1523 2247,1515 2267,1515 2271,1511 2271,1481.36 v2(2286.5,1465.86)
  Bottom Layer w5: v1(670.01,2080) 675.01,2075 1135,2075 1154,2056 1212.75,2056 1223.5,2066.75 1223.5,2067.5 1263.1,2107.1 1398.9,2107.1 1439.5,2066.5 1439.5,1955.07 v1(1427.72,1943.28) ; v1(925.01,1005) 946.33,1026.33 U46.19@946.33,1049.91 ; U27.A13@2271.33,1450.04 2286.5,1465.21 v2(2286.5,1465.86)
PD13: CN4.17 U27.C17 | length 4916.7
  Top Layer w4: CN4.17@4782.49,4030.71 4821.85,3991.34 4821.85,3890.25
  Top Layer w5: v1(4820,3782) 4821.85,3783.85 4821.85,3890.25
  L3_SIG w4: v1(3440,1600) 3557,1717 3557,2067 3575,2085 3575,2215 3738,2378 3738,2837 3663,2912 3663,3175 3645,3193 3645,3515 3860,3730 4731,3730 4783,3782 v1(4820,3782)
  Bottom Layer w5: U27.C17@2397.32,1513.03 2430,1513.02 2485.51,1513.01 2738.52,1260 3100,1260 v1(3440,1600)
PE0: B4.3 B4.4 R224.2 U12.1 U27.F16 | length 4935.1
  Top Layer w5: v1(3578,1750) 3853,1750 3859,1744 3914,1744 3920,1750 5090,1750 5240,1900 5240,2970 5357.28,3087.28 R224.2@5425,3087.28 5428.98,3091.26 U12.1@5466.26,3091.26 B4.3@5569.77,3091.26 B4.4@5790.24,3091.26
  Bottom Layer w5: U27.F16@2365.82,1607.52 2365.82,1607.59 2382.24,1624.01 2468.52,1624.01 2500.52,1592.01 2527.99,1592.01 2815,1305 3085,1305 3530,1750 v1(3578,1750)
PE3: SB30.2 SB59.2 U27.F14 | length 3547.3
  Top Layer w5: v2(2318.52,1591.8) 2329.72,1591.8 2335.52,1585.79 2344.01,1577.3 2345.72,1575.8 2376.41,1575.8 2404.98,1547.23 2404.98,1522.29 2419.77,1507.5 2427.21,1507.5 2476.27,1507.51 2662.78,1321 2701.32,1321 2782,1240.32 3196.48,1240.32 3495.9,940.9 3495.9,856.1 3620,732 3620,393.78 3538.72,312.5 3331.49,312.5 v1(3322,303.01)
  L3_SIG w4: v1(2421.49,331.49) 3293.52,331.49 v1(3322,303.01)
  Bottom Layer w5: U27.F14@2302.83,1607.52 v2(2318.52,1591.8) ; SB59.2@2317.95,225 2380,225 2405,250 2405,315 v1(2421.49,331.49) ; v1(3322,303.01) 3330.01,295 3350,295
PE4: CN13.2 R76.1 U4.4 U4.7 U27.D10 | length 1606
  Top Layer w5: v2(2192.52,1528.8) 2192.52,1522.53 2178.02,1508.03 2178.02,1476.17 2180.48,1473.71 2180.48,1341.54 2206,1316.02 2206,1253.88 2364.88,1095 2669,1095 2779,985 2945,985 3025,905 3025,826.28 R76.1@3002,803.28 3017.69,787.6 U4.7@3017.69,732.14 U4.4@3017.69,699.86 3017.69,677.31 v1(3025,670)
  Bottom Layer w5: U27.D10@2176.84,1544.53 U27.D10@2176.84,1544.53 v2(2192.52,1528.8) ; CN13.2@3010.4,602.35 3010.4,635.4 3025,650 v1(3025,670)
PF1: CN4.18 U27.P4 | length 4426.4
  Top Layer w5: v2(1970.81,1876.41) 1955.5,1891.72 1955.5,1942.49 2002,1988.99 2002,2018 2030,2046 2030,2511.6 2041.9,2523.5 2041.9,2713.38 2463.52,3135 3425,3135 3545,3255 3700,3255 v1(3802.5,3357.5)
  Bottom Layer w4: 4900.6,3855.6 4900.6,3991.33
  Bottom Layer w5: v2(1970.81,1876.41) 1987.73,1859.49 U27.P4@1987.87,1859.49 ; v1(3802.5,3357.5) 3952.5,3357.5 4335,3740 4690,3740 4775,3825 4870,3825 4900.6,3855.6 ; CN4.18@4861.23,4030.71 4900.6,3991.33
PF4: R158.1 R223.2 U27.L2 | length 1639.1
  Top Layer w5: R158.1@1606.3,3157.48 1606.3,3107.82 R223.2@1605.88,3107.4 1605.88,3009.12 1910,2705 1910,2320 1860,2270 1860,2135 1895.31,2099.69 1895.31,2078.78 1901,2073.09 1901,2052.97 1905,2048.97 1905,1992.73 1901,1988.73 1901,1971 1882.71,1952.71 1868.71,1952.71 1827,1911 1827,1863 1909.03,1780.97 v2(1909.03,1780.71)
  Bottom Layer w5: v2(1909.03,1780.71) 1924.74,1765 U27.L2@1924.88,1765
PG5: SB10.1 U27.M4 | length 3788.7
  Top Layer w5: v2(1970.11,1813.11) 1906.89,1813.11 1892.9,1827.1 1892.9,1912.91 1903.68,1923.69 1915.04,1923.69 1923.53,1932.18 1923.53,1943.54 1975,1995.01 1975,2028 2000,2053 2000,2694.99 2455.01,3150 3415,3150 3535,3270 3680,3270 3885,3475 4165,3475 4292.17,3602.17 SB10.1@4292.17,3696.38
  Bottom Layer w5: v2(1970.11,1813.11) 1986.72,1796.5 U27.M4@1987.87,1796.5
PG7: SB29.2 SB55.2 U27.L1 | length 6155.5
  Top Layer w5: v1(800,2515) 840,2555 1315,2555 1395,2635 1445,2635 1487,2593 1487,2528 1570,2445 v1(1570,2435)
  L3_SIG w4: v1(800,2515) 800,2135 924.75,2010.25 924.75,1800.25 951.73,1773.27 1095.67,1773.27 1229,1639.94 1229,1534.94 1292,1471.94 1292,1404 1346,1350 1346,1210.01 1415,1141.01 1415,815 1840,390 1919.49,390 1970.25,339.24 2089.7,339.24 2109.45,319.49 2290.51,319.49 ; v1(2375,335) 2359.49,319.49 2290.51,319.49 ; v1(3295,305) 2305,305 2290.51,319.49
  Bottom Layer w5: v1(1570,2435) 1570,2195.01 1700,2065.01 1700,1985.46 1737.96,1947.5 1744.32,1947.5 1766.82,1925 1788.06,1925 1836,1877.06 1836,1789.8 1860.8,1765 U27.L1@1893.38,1765 ; 2320,360 2350,360 v1(2375,335) ; v1(3295,305) 3295,330 3315,350 SB29.2@3345,350
PG9: CN4.20 U27.T13 | length 4366.6
  Bottom Layer w5: U27.T13@2271.33,1922.48 2255,1938.81 2255,2075.01 2259,2079.01 2259,2108.99 2302.5,2152.49 2302.5,2197.5 2307.5,2202.5 2330.47,2202.5 2351.71,2223.74 2405.08,2223.74 2426.34,2245 2925,2245 3065,2385 3065,2505 3125,2565 3125,2610 3230,2715 3345,2715 3430,2800 4050,2800 4250,3000 4250,3257.56 4345,3352.56 4345,3465 4565,3685 4670,3685 4735,3620 4915,3620 5070,3775 5070,3979.41 CN4.20@5018.71,4030.71
PG14: SB17.1 U27.P6 | length 4048.8
  Top Layer w5: v2(2065.69,1874.32) 2050.62,1889.39 2050.62,1983.72 2087,2020.1 2087,2233 2060,2260 2060,2710.26 2469.74,3120 3431.22,3120 3548.61,3237.39 3717.39,3237.39 3940,3460 4630,3460 4732.52,3562.52 SB17.1@4732.52,3696.38
  Bottom Layer w5: U27.P6@2050.86,1859.49 v2(2065.69,1874.32)
PH0: R155.2 U27.A7 | length 205.8
  Bottom Layer w5: R155.2@2045,1267.72 2058.74,1267.72 2082.35,1291.33 U27.A7@2082.35,1450.04
PH1: R154.2 U27.B7 | length 221.1
  Bottom Layer w5: U27.B7@2082.35,1481.54 2096.92,1466.97 2096.92,1423.9 2100,1420.82 R154.2@2100,1267.72
PH5: SB42.2 U27.F5 | length 4070.2
  Top Layer w5: v1@3535,2135 v1(3540,2130) 3650,2130 3660,2140 4845,2140 4910,2205 v1(4910,2410)
  L3_SIG w4: v2(2035.13,1623.29) 2035.13,1611.58 2049.09,1597.62 2049.09,1582.82 2057.5,1574.41 2072.49,1574.41 2080.69,1566.21 2080.69,1490.31 2101,1470 2108,1470 2204,1374 2204,1366.98 2323.98,1247 2629.92,1247 2680.42,1297.5 3164.33,1297.5 3404.91,1538.08 3404.91,1670.91 3530,1796 3530,2105 3540,2115 v1(3540,2130)
  Bottom Layer w5: U27.F5@2019.36,1607.52 v2(2035.13,1623.29) ; v1(4910,2410) SB42.2@4986.61,2410
PH7: CN4.8 U27.D2 | length 5699.9
  Top Layer w5: v1(4860,3640) 4861.23,3641.23 CN4.8@4861.23,3951.97
  L3_SIG w4: v2(1942.2,1528.5) 1942.2,1527.2 1925,1510 1925,1490 1935,1479.64 1935,1455 1956,1434 1956,1412 1968,1400 2028,1400 2134,1294 2157.02,1294 2288.02,1163 2716.97,1163 2752.56,1198.59 3214.28,1198.59 3855,1839.31 3855,2840 3735,2960 3735,3510 3830,3605 4420,3605 4495,3680 4610,3680 4665,3625 4845,3625 v1(4860,3640)
  Bottom Layer w5: U27.D2@1924.88,1544.53 1940.9,1528.5 v2(1942.2,1528.5)
PN0: R72.2 U27.P17 | length 367.3
  Top Layer w5: v1(2640.5,2019) 2652.36,2030.86 2652.36,2036.34 2672.28,2056.26 R72.2@2672.29,2060
  L3_SIG w4: v2(2412.96,1875.27) 2417.52,1870.71 2475.71,1870.71 2624,2019 v1(2640.5,2019)
  Bottom Layer w5: U27.P17@2397.32,1859.49 2397.31,1859.62 v2(2412.96,1875.27)
PN1: R66.2 U27.R17 | length 336.1
  Top Layer w5: v1(2550,2100) 2550,2097.28 R66.2@2572.28,2075
  L3_SIG w4: v2(2414.72,1906.26) 2415.98,1905 2460,1905 2550,1995 v1(2550,2100)
  Bottom Layer w5: U27.R17@2397.32,1890.99 2397.31,1891.11 2411.2,1905 2413.46,1905 v2(2414.72,1906.26)
PN2: R52.2 U27.T17 | length 301.3
  Top Layer w5: v1(2467.5,2147.5) 2475,2155 R52.2@2497.29,2155
  L3_SIG w4: v2(2380.05,1939.74) 2380.4,1940.09 2380.4,2060.4 v1(2467.5,2147.5)
  Bottom Layer w5: v2(2380.05,1939.74) U27.T17@2397.32,1922.48
PN3: R42.2 U27.R15 | length 292.2
  Top Layer w5: v1(2400,2125) 2402.28,2127.28 R42.2@2402.29,2155
  L3_SIG w4: v2(2349.97,1906.76) 2365.9,1922.69 2365.9,2078.39 2390,2102.49 2390,2115 v1(2400,2125)
  Bottom Layer w5: U27.R15@2334.33,1890.99 2334.32,1891.11 v2(2349.97,1906.76)
PN4: R70.2 U27.N17 | length 335.4
  Top Layer w5: v1(2635,1968.98) 2636.02,1968.98 2637.04,1970 R70.2@2672.29,1970
  L3_SIG w4: v2(2412.14,1842.88) 2414.01,1841.01 2501.01,1841.01 2628.98,1968.98 v1(2635,1968.98)
  Bottom Layer w5: U27.N17@2397.32,1827.99 U27.N17@2397.32,1827.99 v2(2412.14,1842.88)
PN5: R67.2 U27.R16 | length 370.8
  Top Layer w5: v1(2540,2125) R67.2@2572.28,2125
  L3_SIG w4: v2(2381.46,1906.76) 2392.66,1906.76 2407.01,1921.11 2451.11,1921.11 2532.65,2002.65 2532.65,2117.65 v1(2540,2125)
  Bottom Layer w5: U27.R16@2365.82,1890.99 2365.82,1891.12 v2(2381.46,1906.76)
PN6: R71.2 U27.P15 | length 417.4
  Top Layer w5: v1(2635,1993.98) 2651.26,1993.98 R71.2@2672.29,2015
  L3_SIG w4: v2(2349.97,1875.27) 2356.26,1875.27 2373.41,1858.12 2387.41,1858.12 2388.3,1857.23 2492.23,1857.23 2628.98,1993.98 v1(2635,1993.98)
  Bottom Layer w5: U27.P15@2334.33,1859.49 2334.32,1859.62 v2(2349.97,1875.27)
PN7: R216.2 U27.T16 | length 4850.2
  Top Layer w5: v1(2177.9,2592.3) 2170,2584.4 2170,2335 2220.52,2284.48 2220.52,2008.01 2275.84,1952.69 2335.55,1952.69 2348.68,1939.56 v2(2348.68,1939.48)
  L3_SIG w4: v1(305,1500) 558,1753 558,2568 680,2690 680,3320 800,3440 803.02,3440 805.02,3442 1454,3442 1761.7,3134.3 1761.7,3095.7 1825,3032.4 1825,2810 2042.7,2592.3 v1(2177.9,2592.3)
  Bottom Layer w5: R216.2@272.72,1500 v1(305,1500) ; v2(2348.68,1939.48) 2365.68,1922.48 U27.T16@2365.82,1922.48
PN8: R65.2 U27.P16 | length 305.2
  Top Layer w5: v1(2572.28,2005) R65.2@2572.28,2035
  L3_SIG w4: v2(2381.46,1875.27) 2398.45,1892.26 2418.97,1892.26 2423.58,1887.65 2462.65,1887.65 2572.28,1997.28 v1(2572.28,2005)
  Bottom Layer w5: U27.P16@2365.82,1859.49 2365.82,1859.63 v2(2381.46,1875.27)
PN9: R39.2 U27.T15 | length 219.9
  Top Layer w5: v1(2320,2095) R39.2@2320,2122.28
  L3_SIG w4: v2(2318.48,1938.19) 2335.52,1955.23 2335.52,2079.48 v1(2320,2095)
  Bottom Layer w5: v2(2318.48,1938.19) 2334.19,1922.48 U27.T15@2334.33,1922.48
PN10: R37.2 U27.U15 | length 190.8
  Top Layer w5: v1(2280,2095) R37.2@2280,2122.28
  L3_SIG w4: v1(2280,2095) 2321.52,2053.48 v2(2321.52,1975.4)
  Bottom Layer w5: v2(2321.52,1975.4) 2321.52,1966.72 U27.U15@2334.33,1953.98 U27.U15@2334.33,1953.98
PN11: R40.2 U27.U16 | length 177.9
  Top Layer w5: v1(2360,2097.24) R40.2@2360,2122.28
  L3_SIG w4: v2(2351.35,1969.9) 2351.38,2085 2351.38,2088.62 v1(2360,2097.24)
  Bottom Layer w5: v2(2351.35,1969.9) 2351.35,1968.31 2365.68,1953.98 U27.U16@2365.82,1953.98
PN12: CN13.10 R143.1 U27.P14 | length 4214.4
  Top Layer w5: v1(2863,1912) 2882.17,1892.83 2909.17,1892.83 2932,1870 3040,1870 3054,1884 3054,1900 3068,1914 3385,1914 3529,1770 3885.01,1770 v1(3887.51,1767.5)
  L3_SIG w4: v2(2318.47,1875.27) 2324.73,1875.27 2340,1860 2355,1860 2365,1850 2365,1840 2376.12,1828.88 2567.88,1828.88 2624,1885 2845,1885 2863,1903 v1(2863,1912)
  Bottom Layer w5: U27.P14@2302.83,1859.49 2302.82,1859.62 v2(2318.47,1875.27) ; CN13.10@2664.22,200.78 CN13.10@2669.85,200.78 2586.12,200.78 2486.02,300.88 R143.1@2486.02,414.1 2486.02,539.02 2767,820 3060,820 3155,915 3155,960 3405,1210 3405,1289.99 3882.51,1767.5 v1(3887.51,1767.5)
PO0: R61.2 U27.M17 | length 213.6
  Top Layer w5: v2(2412.14,1811.39) 2412.76,1812.01 2417,1812.01 2461.27,1856.28 2531.71,1856.28 2559.09,1828.9 2566.18,1828.9 R61.2@2572.29,1835
  Bottom Layer w5: U27.M17@2397.32,1796.5 2397.31,1796.56 v2(2412.14,1811.39)
PO2: R58.2 U27.K17 | length 188.9
  Top Layer w5: v2(2434.12,1724.5) 2435,1724.5 2438.22,1721.28 2532.72,1721.28 2554,1700 R58.2@2572.29,1700
  Bottom Layer w5: U27.K17@2397.32,1733.51 2425.11,1733.51 v2(2434.12,1724.5)
PO3: R51.2 U27.M16 | length 151.1
  Top Layer w5: v2(2380.64,1811.39) 2396.26,1827.01 2417,1827.01 2469.99,1880 R51.2@2482.29,1880
  Bottom Layer w5: U27.M16@2365.82,1796.5 2365.82,1796.57 v2(2380.64,1811.39)
PO4: R62.2 U27.N16 | length 260.9
  Top Layer w5: v2(2381.46,1843.77) 2393.23,1843.77 2397.64,1848.18 2397.64,1848.89 2406.13,1857.38 2417.37,1857.38 2434.99,1875 2448,1875 2454,1881 2454,1896.27 2459.01,1901.28 2543.72,1901.28 2550,1895 2550,1885 2555,1880 R62.2@2572.29,1880
  Bottom Layer w5: U27.N16@2365.82,1827.99 2365.82,1828.13 v2(2381.46,1843.77)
